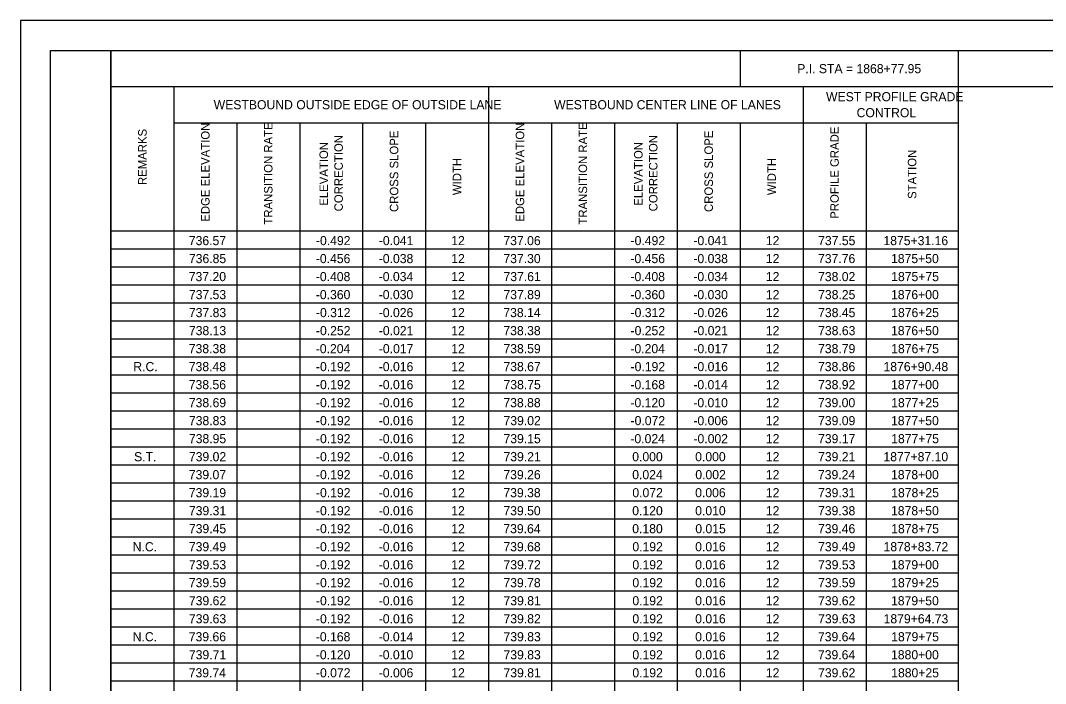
# Model space of a CAD drawing. Extents: x -174 to 34, y 0 to 22.
# Drawn here: x 0 to 17, y 11 to 22 of the extents above; entities that cross this region are included whole.
import ezdxf

# ---------------------------------------------------------------- set-up
doc = ezdxf.new("R2010")
doc.units = 0
for name, color, linetype in [('Default', 7, 'Continuous'), ('SH_Border', 7, 'Continuous'), ('SH_Cut_Line', 7, 'Continuous')]:
    doc.layers.add(name, color=color, linetype=linetype)

msp = doc.modelspace()

# ---------------------------------------------------------------- linework, layer by layer
at = {"layer": 'Default'}
for p, q in [((1.5, 21.5), (32, 21.5)), ((1.5, 21.5), (1.5, 2.37)), ((11.936, 21.5), (11.936, 20.903)), ((15.553, 21.5), (15.553, 2.37)), ((1.5, 20.903), (32, 20.903)), ((2.544, 20.903), (2.544, 18.513)), ((7.761, 20.903), (7.761, 18.513)), ((12.979, 20.903), (12.979, 18.513)), ((2.544, 20.305), (15.553, 20.305)), ((3.587, 20.305), (3.587, 18.513)), ((4.631, 20.305), (4.631, 18.513)), ((5.674, 20.305), (5.674, 18.513)), ((6.718, 20.305), (6.718, 18.513)), ((8.805, 20.305), (8.805, 18.513)), ((9.849, 20.305), (9.849, 18.513)), ((10.892, 20.305), (10.892, 18.513)), ((11.936, 20.305), (11.936, 18.513)), ((14.023, 20.305), (14.023, 18.513)), ((1.5, 18.513), (15.553, 18.513)), ((2.544, 18.513), (2.544, 2.37)), ((3.587, 18.513), (3.587, 2.37)), ((4.631, 18.513), (4.631, 2.37)), ((5.674, 18.513), (5.674, 2.37)), ((6.718, 18.513), (6.718, 2.37)), ((7.761, 18.513), (7.761, 2.37)), ((8.805, 18.513), (8.805, 2.37)), ((9.849, 18.513), (9.849, 2.37)), ((10.892, 18.513), (10.892, 2.37)), ((11.936, 18.513), (11.936, 2.37)), ((12.979, 18.513), (12.979, 2.37)), ((14.023, 18.513), (14.023, 2.37)), ((1.5, 18.215), (15.553, 18.215)), ((1.5, 17.916), (15.553, 17.916)), ((1.5, 17.617), (15.553, 17.617)), ((1.5, 17.319), (15.553, 17.319)), ((1.5, 17.02), (15.553, 17.02)), ((1.5, 16.721), (15.553, 16.721)), ((1.5, 16.423), (15.553, 16.423)), ((1.5, 16.124), (15.553, 16.124)), ((1.5, 15.825), (15.553, 15.825)), ((1.5, 15.527), (15.553, 15.527)), ((1.5, 15.228), (15.553, 15.228)), ((1.5, 14.929), (15.553, 14.929)), ((1.5, 14.631), (15.553, 14.631)), ((1.5, 14.332), (15.553, 14.332)), ((1.5, 14.033), (15.553, 14.033)), ((1.5, 13.735), (15.553, 13.735)), ((1.5, 13.436), (15.553, 13.436)), ((1.5, 13.137), (15.553, 13.137)), ((1.5, 12.839), (15.553, 12.839)), ((1.5, 12.54), (15.553, 12.54)), ((1.5, 12.241), (15.553, 12.241)), ((1.5, 11.943), (15.553, 11.943)), ((1.5, 11.644), (15.553, 11.644)), ((1.5, 11.345), (15.553, 11.345)), ((1.5, 11.047), (15.553, 11.047))]:
    msp.add_line(p, q, dxfattribs=at)
at = {"layer": 'SH_Border'}
for points in [[(0.5, 21.5), (1.5, 21.5), (1.5, 0.5), (0.5, 0.5)], [(1.5, 21.5), (33.5, 21.5), (33.5, 0.5), (1.5, 0.5)]]:
    msp.add_lwpolyline(points, close=True, dxfattribs=at)
at = {"layer": 'SH_Cut_Line'}
msp.add_lwpolyline([(0, 0), (34, 0), (34, 22), (0, 22)], close=True, dxfattribs=at)

# ---------------------------------------------------------------- texts
at = {"layer": 'Default'}
for s, height, p in [('P.I. STA = 1868+77.95', 0.15112, (12.882, 21.126)), ('WEST PROFILE GRADE ', 0.15112, (13.36, 20.661)), ('WESTBOUND OUTSIDE EDGE OF OUTSIDE LANE', 0.15112, (3.204, 20.528)), ('WESTBOUND CENTER LINE OF LANES', 0.15112, (8.85, 20.528)), ('CONTROL', 0.1511, (13.867, 20.396)), ('736.57', 0.1511, (2.792, 18.274)), ('-0.492', 0.1511, (4.9, 18.274)), ('-0.041', 0.1511, (5.943, 18.274)), ('12', 0.1511, (7.144, 18.274)), ('737.06', 0.1511, (8.009, 18.274)), ('-0.492', 0.1511, (10.118, 18.274)), ('-0.041', 0.1511, (11.161, 18.274)), ('12', 0.1511, (12.362, 18.274)), ('737.55', 0.1511, (13.229, 18.274)), ('1875+31.16', 0.1511, (14.312, 18.274)), ('736.85', 0.1511, (2.793, 17.976)), ('-0.456', 0.1511, (4.898, 17.976)), ('-0.038', 0.1511, (5.942, 17.976)), ('12', 0.1511, (7.144, 17.976)), ('737.30', 0.1511, (8.009, 17.976)), ('-0.456', 0.1511, (10.116, 17.976)), ('-0.038', 0.1511, (11.16, 17.976)), ('12', 0.1511, (12.362, 17.976)), ('737.76', 0.1511, (13.227, 17.976)), ('1875+50', 0.1511, (14.438, 17.976)), ('737.20', 0.1511, (2.791, 17.677)), ('-0.408', 0.1511, (4.898, 17.677)), ('-0.034', 0.1511, (5.941, 17.677)), ('12', 0.1511, (7.144, 17.677)), ('737.61', 0.1511, (8.011, 17.677)), ('-0.408', 0.1511, (10.116, 17.677)), ('-0.034', 0.1511, (11.159, 17.677)), ('12', 0.1511, (12.362, 17.677)), ('738.02', 0.1511, (13.228, 17.677)), ('1875+75', 0.1511, (14.441, 17.677)), ('737.53', 0.1511, (2.793, 17.378)), ('-0.360', 0.1511, (4.898, 17.378)), ('-0.030', 0.1511, (5.941, 17.378)), ('12', 0.1511, (7.144, 17.378)), ('737.89', 0.1511, (8.01, 17.378)), ('-0.360', 0.1511, (10.116, 17.378)), ('-0.030', 0.1511, (11.159, 17.378)), ('12', 0.1511, (12.362, 17.378)), ('738.25', 0.1511, (13.229, 17.378)), ('1876+00', 0.1511, (14.438, 17.378)), ('737.83', 0.1511, (2.793, 17.08)), ('-0.312', 0.1511, (4.9, 17.08)), ('-0.026', 0.1511, (5.942, 17.08)), ('12', 0.1511, (7.144, 17.08)), ('738.14', 0.1511, (8.008, 17.08)), ('-0.312', 0.1511, (10.118, 17.08)), ('-0.026', 0.1511, (11.16, 17.08)), ('12', 0.1511, (12.362, 17.08)), ('738.45', 0.1511, (13.229, 17.08)), ('1876+25', 0.1511, (14.441, 17.08)), ('738.13', 0.1511, (2.793, 16.781)), ('-0.252', 0.1511, (4.9, 16.781)), ('-0.021', 0.1511, (5.943, 16.781)), ('12', 0.1511, (7.144, 16.781)), ('738.38', 0.1511, (8.009, 16.781)), ('-0.252', 0.1511, (10.118, 16.781)), ('-0.021', 0.1511, (11.161, 16.781)), ('12', 0.1511, (12.362, 16.781)), ('738.63', 0.1511, (13.229, 16.781)), ('1876+50', 0.1511, (14.438, 16.781)), ('738.38', 0.1511, (2.791, 16.482)), ('-0.204', 0.1511, (4.897, 16.482)), ('-0.017', 0.1511, (5.943, 16.482)), ('12', 0.1511, (7.144, 16.482)), ('738.59', 0.1511, (8.01, 16.482)), ('-0.204', 0.1511, (10.115, 16.482)), ('-0.017', 0.1511, (11.16, 16.482)), ('12', 0.1511, (12.362, 16.482)), ('738.79', 0.1511, (13.228, 16.482)), ('1876+75', 0.1511, (14.441, 16.482)), ('R.C.', 0.1511, (1.871, 16.184)), ('738.48', 0.1511, (2.791, 16.184)), ('-0.192', 0.1511, (4.9, 16.184)), ('-0.016', 0.1511, (5.942, 16.184)), ('12', 0.1511, (7.144, 16.184)), ('738.67', 0.1511, (8.01, 16.184)), ('-0.192', 0.1511, (10.118, 16.184)), ('-0.016', 0.1511, (11.16, 16.184)), ('12', 0.1511, (12.362, 16.184)), ('738.86', 0.1511, (13.227, 16.184)), ('1876+90.48', 0.1511, (14.313, 16.184)), ('738.56', 0.1511, (2.791, 15.885)), ('-0.192', 0.1511, (4.9, 15.885)), ('-0.016', 0.1511, (5.942, 15.885)), ('12', 0.1511, (7.144, 15.885)), ('738.75', 0.1511, (8.011, 15.885)), ('-0.168', 0.1511, (10.116, 15.885)), ('-0.014', 0.1511, (11.159, 15.885)), ('12', 0.1511, (12.362, 15.885)), ('738.92', 0.1511, (13.228, 15.885)), ('1877+00', 0.1511, (14.438, 15.885)), ('738.69', 0.1511, (2.792, 15.586)), ('-0.192', 0.1511, (4.9, 15.586)), ('-0.016', 0.1511, (5.942, 15.586)), ('12', 0.1511, (7.144, 15.586)), ('738.88', 0.1511, (8.009, 15.586)), ('-0.120', 0.1511, (10.116, 15.586)), ('-0.010', 0.1511, (11.159, 15.586)), ('12', 0.1511, (12.362, 15.586)), ('739.00', 0.1511, (13.226, 15.586)), ('1877+25', 0.1511, (14.441, 15.586)), ('738.83', 0.1511, (2.793, 15.288)), ('-0.192', 0.1511, (4.9, 15.288)), ('-0.016', 0.1511, (5.942, 15.288)), ('12', 0.1511, (7.144, 15.288)), ('739.02', 0.1511, (8.011, 15.288)), ('-0.072', 0.1511, (10.118, 15.288)), ('-0.006', 0.1511, (11.16, 15.288)), ('12', 0.1511, (12.362, 15.288)), ('739.09', 0.1511, (13.228, 15.288)), ('1877+50', 0.1511, (14.438, 15.288)), ('738.95', 0.1511, (2.793, 14.989)), ('-0.192', 0.1511, (4.9, 14.989)), ('-0.016', 0.1511, (5.942, 14.989)), ('12', 0.1511, (7.144, 14.989)), ('739.15', 0.1511, (8.011, 14.989)), ('-0.024', 0.1511, (10.115, 14.989)), ('-0.002', 0.1511, (11.161, 14.989)), ('12', 0.1511, (12.362, 14.989)), ('739.17', 0.1511, (13.228, 14.989)), ('1877+75', 0.1511, (14.441, 14.989)), ('S.T.', 0.1511, (1.884, 14.69)), ('739.02', 0.1511, (2.793, 14.69)), ('-0.192', 0.1511, (4.9, 14.69)), ('-0.016', 0.1511, (5.942, 14.69)), ('12', 0.1511, (7.144, 14.69)), ('739.21', 0.1511, (8.011, 14.69)), ('0.000', 0.1511, (10.146, 14.69)), ('0.000', 0.1511, (11.19, 14.69)), ('12', 0.1511, (12.362, 14.69)), ('739.21', 0.1511, (13.228, 14.69)), ('1877+87.10', 0.1511, (14.312, 14.69)), ('739.07', 0.1511, (2.792, 14.392)), ('-0.192', 0.1511, (4.9, 14.392)), ('-0.016', 0.1511, (5.942, 14.392)), ('12', 0.1511, (7.144, 14.392)), ('739.26', 0.1511, (8.009, 14.392)), ('0.024', 0.1511, (10.146, 14.392)), ('0.002', 0.1511, (11.192, 14.392)), ('12', 0.1511, (12.362, 14.392)), ('739.24', 0.1511, (13.226, 14.392)), ('1878+00', 0.1511, (14.438, 14.392)), ('739.19', 0.1511, (2.792, 14.093)), ('-0.192', 0.1511, (4.9, 14.093)), ('-0.016', 0.1511, (5.942, 14.093)), ('12', 0.1511, (7.144, 14.093)), ('739.38', 0.1511, (8.009, 14.093)), ('0.072', 0.1511, (10.148, 14.093)), ('0.006', 0.1511, (11.19, 14.093)), ('12', 0.1511, (12.362, 14.093)), ('739.31', 0.1511, (13.228, 14.093)), ('1878+25', 0.1511, (14.441, 14.093)), ('739.31', 0.1511, (2.793, 13.794)), ('-0.192', 0.1511, (4.9, 13.794)), ('-0.016', 0.1511, (5.942, 13.794)), ('12', 0.1511, (7.144, 13.794)), ('739.50', 0.1511, (8.009, 13.794)), ('0.120', 0.1511, (10.146, 13.794)), ('0.010', 0.1511, (11.19, 13.794)), ('12', 0.1511, (12.362, 13.794)), ('739.38', 0.1511, (13.227, 13.794)), ('1878+50', 0.1511, (14.438, 13.794)), ('739.45', 0.1511, (2.793, 13.496)), ('-0.192', 0.1511, (4.9, 13.496)), ('-0.016', 0.1511, (5.942, 13.496)), ('12', 0.1511, (7.144, 13.496)), ('739.64', 0.1511, (8.008, 13.496)), ('0.180', 0.1511, (10.146, 13.496)), ('0.015', 0.1511, (11.192, 13.496)), ('12', 0.1511, (12.362, 13.496)), ('739.46', 0.1511, (13.227, 13.496)), ('1878+75', 0.1511, (14.441, 13.496)), ('N.C.', 0.1511, (1.861, 13.197)), ('739.49', 0.1511, (2.792, 13.197)), ('-0.192', 0.1511, (4.9, 13.197)), ('-0.016', 0.1511, (5.942, 13.197)), ('12', 0.1511, (7.144, 13.197)), ('739.68', 0.1511, (8.009, 13.197)), ('0.192', 0.1511, (10.148, 13.197)), ('0.016', 0.1511, (11.19, 13.197)), ('12', 0.1511, (12.362, 13.197)), ('739.49', 0.1511, (13.228, 13.197)), ('1878+83.72', 0.1511, (14.314, 13.197)), ('739.53', 0.1511, (2.793, 12.898)), ('-0.192', 0.1511, (4.9, 12.898)), ('-0.016', 0.1511, (5.942, 12.898)), ('12', 0.1511, (7.144, 12.898)), ('739.72', 0.1511, (8.011, 12.898)), ('0.192', 0.1511, (10.148, 12.898)), ('0.016', 0.1511, (11.19, 12.898)), ('12', 0.1511, (12.362, 12.898)), ('739.53', 0.1511, (13.229, 12.898)), ('1879+00', 0.1511, (14.438, 12.898)), ('739.59', 0.1511, (2.792, 12.6)), ('-0.192', 0.1511, (4.9, 12.6)), ('-0.016', 0.1511, (5.942, 12.6)), ('12', 0.1511, (7.144, 12.6)), ('739.78', 0.1511, (8.009, 12.6)), ('0.192', 0.1511, (10.148, 12.6)), ('0.016', 0.1511, (11.19, 12.6)), ('12', 0.1511, (12.362, 12.6)), ('739.59', 0.1511, (13.228, 12.6)), ('1879+25', 0.1511, (14.441, 12.6)), ('739.62', 0.1511, (2.793, 12.301)), ('-0.192', 0.1511, (4.9, 12.301)), ('-0.016', 0.1511, (5.942, 12.301)), ('12', 0.1511, (7.144, 12.301)), ('739.81', 0.1511, (8.011, 12.301)), ('0.192', 0.1511, (10.148, 12.301)), ('0.016', 0.1511, (11.19, 12.301)), ('12', 0.1511, (12.362, 12.301)), ('739.62', 0.1511, (13.228, 12.301)), ('1879+50', 0.1511, (14.438, 12.301)), ('739.63', 0.1511, (2.793, 12.002)), ('-0.192', 0.1511, (4.9, 12.002)), ('-0.016', 0.1511, (5.942, 12.002)), ('12', 0.1511, (7.144, 12.002)), ('739.82', 0.1511, (8.011, 12.002)), ('0.192', 0.1511, (10.148, 12.002)), ('0.016', 0.1511, (11.19, 12.002)), ('12', 0.1511, (12.362, 12.002)), ('739.63', 0.1511, (13.229, 12.002)), ('1879+64.73', 0.1511, (14.315, 12.002)), ('N.C.', 0.1511, (1.861, 11.704)), ('739.66', 0.1511, (2.791, 11.704)), ('-0.168', 0.1511, (4.898, 11.704)), ('-0.014', 0.1511, (5.941, 11.704)), ('12', 0.1511, (7.144, 11.704)), ('739.83', 0.1511, (8.011, 11.704)), ('0.192', 0.1511, (10.148, 11.704)), ('0.016', 0.1511, (11.19, 11.704)), ('12', 0.1511, (12.362, 11.704)), ('739.64', 0.1511, (13.226, 11.704)), ('1879+75', 0.1511, (14.441, 11.704)), ('739.71', 0.1511, (2.793, 11.405)), ('-0.120', 0.1511, (4.898, 11.405)), ('-0.010', 0.1511, (5.941, 11.405)), ('12', 0.1511, (7.144, 11.405)), ('739.83', 0.1511, (8.011, 11.405)), ('0.192', 0.1511, (10.148, 11.405)), ('0.016', 0.1511, (11.19, 11.405)), ('12', 0.1511, (12.362, 11.405)), ('739.64', 0.1511, (13.226, 11.405)), ('1880+00', 0.1511, (14.438, 11.405)), ('739.74', 0.1511, (2.79, 11.106)), ('-0.072', 0.1511, (4.9, 11.106)), ('-0.006', 0.1511, (5.942, 11.106)), ('12', 0.1511, (7.144, 11.106)), ('739.81', 0.1511, (8.011, 11.106)), ('0.192', 0.1511, (10.148, 11.106)), ('0.016', 0.1511, (11.19, 11.106)), ('12', 0.1511, (12.362, 11.106)), ('739.62', 0.1511, (13.228, 11.106)), ('1880+25', 0.1511, (14.441, 11.106))]:
    msp.add_text(s, height=height, dxfattribs=at).set_placement(p)
for s, height, p in [('EDGE ELEVATION', 0.14081, (3.136, 18.663)), ('TRANSITION RATE', 0.14081, (4.179, 18.615)), ('EDGE ELEVATION', 0.14081, (8.354, 18.663)), ('TRANSITION RATE', 0.14081, (9.397, 18.615)), ('PROFILE GRADE', 0.14081, (13.571, 18.712)), ('REMARKS', 0.1408, (2.092, 19.271)), ('CORRECTION', 0.1408, (5.346, 18.835)), ('CROSS SLOPE', 0.14081, (6.266, 18.824)), ('CORRECTION', 0.1408, (10.564, 18.835)), ('CROSS SLOPE', 0.14081, (11.484, 18.824)), ('ELEVATION ', 0.1408, (5.1, 18.928)), ('ELEVATION ', 0.1408, (10.318, 18.928)), ('STATION', 0.1408, (14.858, 19.041)), ('WIDTH', 0.1408, (7.31, 19.104)), ('WIDTH', 0.1408, (12.528, 19.104))]:
    msp.add_text(s, height=height, rotation=90, dxfattribs=at).set_placement(p)

doc.saveas('drawing.dxf')
